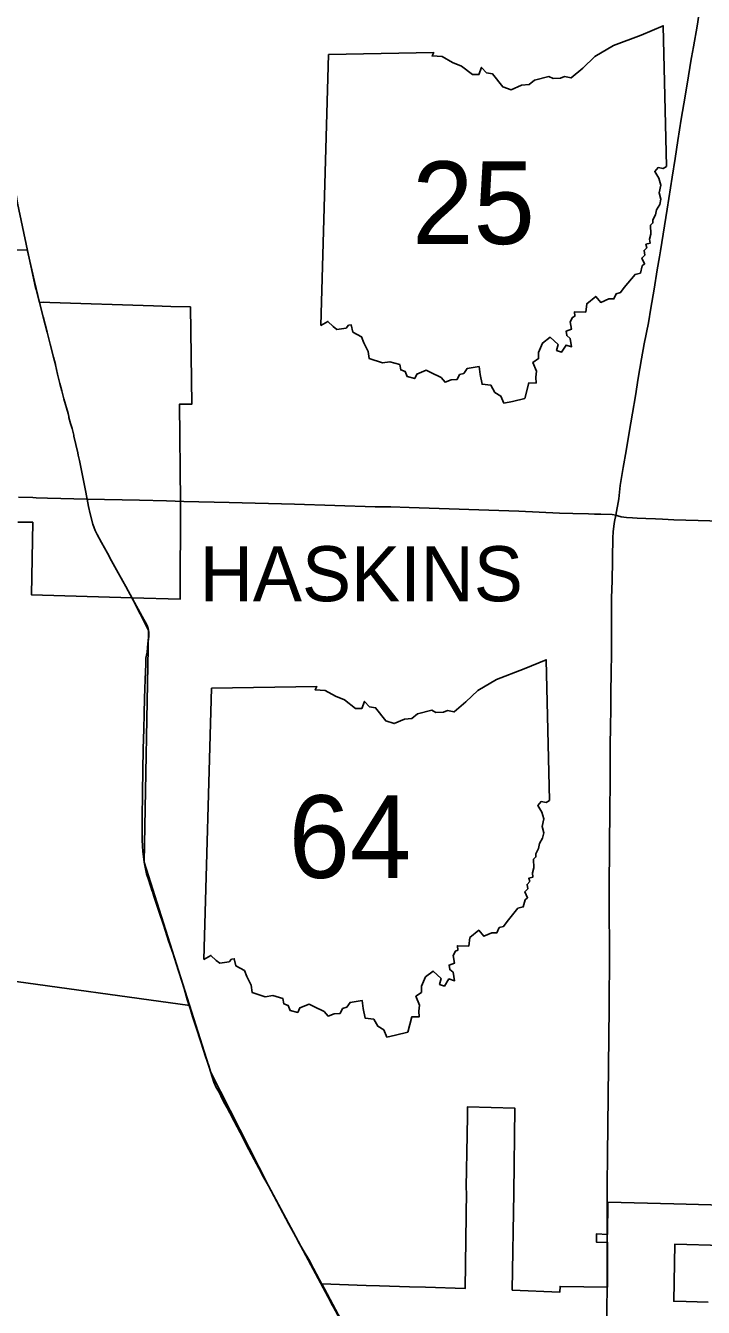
# Model space of a CAD drawing. Extents: x 0 to 851, y 0 to 440.
# Drawn here: x 287.6 to 318.5, y 226.5 to 285 of the extents above; entities that cross this region are included whole.
import ezdxf

# ---------------------------------------------------------------- set-up
doc = ezdxf.new("R2010")
doc.units = 0
for name, color, linetype in [('DV_X_Corp_Line', 7, 'Continuous'), ('GM_X_Corporation_Text', 7, 'Continuous'), ('GM_X_State_Route', 7, 'Continuous'), ('PV_P_Text', 7, 'Continuous'), ('RD_P_Fence', 7, 'Continuous'), ('SH_Data', 7, 'Continuous')]:
    doc.layers.add(name, color=color, linetype=linetype)

msp = doc.modelspace()

# ---------------------------------------------------------------- linework, layer by layer
at = {"layer": 'DV_X_Corp_Line'}
for points in [[(285.628, 274.777), (287.638, 274.782), (287.673, 274.604), (287.962, 273.347), (288.204, 272.386), (288.39, 272.391), (288.666, 272.381), (293.406, 272.229), (294.195, 272.205), (295.084, 272.179), (295.145, 267.74), (294.593, 267.747), (294.636, 263.311), (294.612, 258.847), (292.419, 258.917), (287.825, 259.049), (287.89, 262.358), (287.214, 262.364)], [(303.326, 223.42), (301.088, 227.615), (303.104, 227.549), (303.717, 227.53), (305.091, 227.491), (305.822, 227.467), (307.622, 227.403), (307.687, 231.84), (307.68, 231.909), (307.678, 231.954), (307.677, 232.034), (307.69, 232.835), (307.704, 233.603), (307.734, 235.274), (307.74, 235.698), (309.898, 235.629), (309.843, 231.766), (309.776, 227.337), (311.949, 227.247), (311.958, 227.5), (314.128, 227.473), (314.127, 229.51), (313.616, 229.524), (313.62, 229.896), (314.127, 229.874), (314.134, 231.341), (317.154, 231.265), (319.399, 231.202)], [(319.371, 229.365), (317.197, 229.427), (317.149, 226.828), (317.713, 226.813), (318.72, 226.789)]]:
    msp.add_lwpolyline(points, dxfattribs=at)
at = {"layer": 'GM_X_State_Route'}
for points in [[(317.965, 283.565), (318.056, 284.051), (318.21, 284.99), (318.342, 285.798), (318.465, 286.621), (318.58, 287.355), (318.674, 287.903), (318.734, 288.303), (318.84, 288.954), (318.934, 289.522), (319.023, 290.102), (319.081, 290.432)], [(314.502, 262.675), (314.639, 263.434), (314.703, 264.038), (314.84, 264.849), (314.974, 265.619), (315.115, 266.456), (315.271, 267.334), (315.395, 268.121), (315.529, 268.932), (315.681, 269.816), (315.79, 270.492), (315.997, 271.461), (316.106, 272.124), (316.255, 272.998), (316.397, 273.879), (316.493, 274.459), (316.536, 274.737), (316.724, 275.881), (316.841, 276.641), (316.921, 277.133), (317.075, 278.092), (317.216, 278.949), (317.34, 279.774), (317.491, 280.745), (317.662, 281.791), (317.819, 282.715), (317.949, 283.478), (317.965, 283.565)], [(287.654, 274.76), (287.187, 276.916), (286.85, 279.198), (286.876, 279.819), (286.892, 280.43), (286.918, 281.178), (286.936, 281.82), (286.964, 282.464), (286.986, 282.978), (286.992, 283.339), (286.992, 283.342)], [(287.883, 273.701), (287.654, 274.76)], [(288.036, 272.996), (287.883, 273.701)], [(288.196, 272.384), (288.039, 272.981), (288.036, 272.996)], [(288.927, 269.548), (288.839, 269.883), (288.686, 270.485), (288.551, 271.033), (288.372, 271.728), (288.196, 272.384)], [(289.542, 267.141), (289.531, 267.184), (289.499, 267.325), (289.313, 267.994), (289.221, 268.349), (289.128, 268.686), (289.022, 269.115), (288.929, 269.541), (288.927, 269.548)], [(289.771, 266.284), (289.759, 266.338), (289.688, 266.636), (289.608, 266.867), (289.542, 267.141)], [(289.969, 265.419), (289.944, 265.522), (289.861, 265.903), (289.771, 266.284)], [(290.37, 263.418), (290.287, 263.882), (290.14, 264.564), (290.028, 265.173), (289.969, 265.419)], [(287.241, 263.51), (287.893, 263.485), (288.045, 263.479)], [(288.045, 263.479), (288.56, 263.456), (290.37, 263.418)], [(292.432, 258.882), (292.422, 258.899), (292.244, 259.224), (292.134, 259.428), (292.002, 259.667), (291.714, 260.192), (291.49, 260.603), (291.297, 260.955), (291.034, 261.435), (290.834, 261.807), (290.738, 261.99), (290.696, 262.107), (290.636, 262.27), (290.508, 262.736), (290.441, 263.078), (290.37, 263.418)], [(290.37, 263.418), (290.37, 263.418), (292.768, 263.364), (293.991, 263.331), (294.779, 263.31)], [(294.779, 263.31), (296.848, 263.255), (299.841, 263.178), (303.525, 263.069), (304.241, 263.058), (305.074, 263.039), (310.069, 262.867), (311.933, 262.778), (312.546, 262.758), (313.25, 262.736), (313.53, 262.731)], [(313.53, 262.731), (313.813, 262.726), (314.335, 262.711), (314.502, 262.675)], [(314.205, 245.738), (314.229, 249.324), (314.229, 249.431), (314.241, 250.307), (314.248, 251.318), (314.252, 252.167), (314.267, 253.053), (314.276, 253.814), (314.272, 254.581), (314.284, 255.501), (314.299, 256.351), (314.299, 257.187), (314.307, 258.073), (314.311, 258.896), (314.342, 259.698), (314.352, 260.596), (314.354, 261.034), (314.366, 261.335), (314.368, 261.641), (314.382, 261.919), (314.41, 262.173), (314.441, 262.399), (314.502, 262.675)], [(314.502, 262.675), (314.596, 262.646), (314.747, 262.606), (314.989, 262.58), (315.271, 262.555)], [(315.271, 262.555), (315.472, 262.538), (315.878, 262.523), (316.321, 262.509)], [(316.321, 262.509), (316.63, 262.498), (317.153, 262.476), (317.702, 262.46), (318.268, 262.444), (318.801, 262.422), (319.494, 262.4), (320.053, 262.381), (320.586, 262.365), (321.196, 262.341), (321.765, 262.322), (322.371, 262.302), (323.021, 262.281), (323.647, 262.26), (324.13, 262.246), (324.468, 262.233), (324.803, 262.218), (325.399, 262.187), (325.938, 262.159), (325.958, 262.158), (325.96, 262.158)], [(301.768, 226.305), (301.532, 226.708), (301.343, 227.139), (301.114, 227.552), (300.702, 228.321), (300.487, 228.726), (300.275, 229.075), (300.025, 229.527), (299.875, 229.799), (299.574, 230.348), (299.16, 231.114), (298.906, 231.6), (298.645, 232.097), (298.429, 232.484), (298.211, 232.9), (298.001, 233.293), (297.637, 233.973), (297.363, 234.521), (297.083, 235.047), (296.885, 235.426), (296.766, 235.653), (296.618, 235.901), (296.474, 236.2), (296.363, 236.412), (296.267, 236.582), (296.157, 236.823), (296.021, 237.262), (295.927, 237.558), (295.772, 237.996), (295.563, 238.653), (295.353, 239.309), (295.188, 239.815), (295.087, 240.137), (294.94, 240.587), (294.797, 241.092), (294.696, 241.43), (294.441, 242.225), (294.293, 242.674), (294.09, 243.27), (294.016, 243.502), (293.868, 243.943), (293.629, 244.668), (293.418, 245.303), (293.352, 245.51), (293.343, 245.538), (293.271, 245.768), (293.168, 246.069), (293.087, 246.319), (293.025, 246.624), (292.978, 246.851), (292.942, 247.09), (292.913, 247.336), (292.899, 247.591), (292.882, 247.878), (292.878, 248.305), (292.883, 248.567), (292.889, 249.014), (292.891, 249.236), (292.896, 249.643), (292.902, 250.032), (292.936, 252.029), (292.958, 252.926), (292.977, 253.624), (292.995, 254.329), (293.02, 255.191), (293.045, 255.886), (293.049, 256.161), (293.11, 256.439), (293.146, 256.83), (293.169, 257.029), (293.183, 257.149), (293.189, 257.276), (293.187, 257.344), (293.176, 257.435), (293.162, 257.514), (293.126, 257.607), (293.079, 257.704), (292.962, 257.921), (292.798, 258.229), (292.533, 258.699), (292.432, 258.882)], [(314.109, 232.126), (314.122, 233.491), (314.201, 240.218), (314.216, 242.725), (314.2, 244.884), (314.205, 245.738)], [(314.107, 231.246), (314.107, 231.276), (314.108, 232.041), (314.109, 232.126)], [(314.105, 229.745), (314.107, 231.246)], [(314.102, 227.362), (314.104, 229.392)], [(314.104, 229.392), (314.104, 229.423), (314.105, 229.737), (314.105, 229.745)], [(314.081, 225.01), (314.1, 226.925)], [(314.1, 226.925), (314.101, 227.008), (314.102, 227.362)]]:
    msp.add_lwpolyline(points, dxfattribs=at)
at = {"layer": 'PV_P_Text'}
for p, q in [((301.045, 271.329), (301.391, 283.701)), ((301.045, 271.329), (301.391, 283.701)), ((295.704, 242.416), (296.05, 254.788)), ((295.704, 242.416), (296.05, 254.788))]:
    msp.add_line(p, q, dxfattribs=at)
for points in [[(301.391, 283.701), (306.192, 283.782), (306.117, 283.632), (306.57, 283.601), (307.051, 283.337), (307.458, 283.17), (307.956, 282.776), (308.253, 282.781), (308.379, 283.103), (308.607, 282.854), (308.878, 282.81), (309.346, 282.218), (309.732, 282.089), (310.195, 282.292), (310.541, 282.326), (310.794, 282.526), (311.452, 282.698), (311.636, 282.595), (311.985, 282.616), (312.16, 282.692), (312.465, 282.624), (313, 283.074), (313.551, 283.604), (314.399, 284.105), (315.665, 284.579), (316.667, 285.003), (316.811, 278.582)], [(301.391, 283.701), (306.192, 283.782), (306.117, 283.632), (306.57, 283.601), (307.051, 283.337), (307.458, 283.17), (307.956, 282.776), (308.253, 282.781), (308.379, 283.103), (308.607, 282.854), (308.878, 282.81), (309.346, 282.218), (309.732, 282.089), (310.195, 282.292), (310.541, 282.326), (310.794, 282.526), (311.452, 282.698), (311.636, 282.595), (311.985, 282.616), (312.16, 282.692), (312.465, 282.624), (313, 283.074), (313.551, 283.604), (314.399, 284.105), (315.665, 284.579), (316.667, 285.003), (316.811, 278.582)], [(316.811, 278.582), (316.664, 278.492), (316.433, 278.535), (316.279, 278.355), (316.47, 278.054), (316.561, 277.737), (316.481, 277.387), (316.56, 277.098), (316.506, 276.857), (316.361, 276.616), (316.311, 276.387), (316.189, 276.146), (316.199, 276.011), (316.081, 275.904), (316.103, 275.502), (316.043, 275.279), (316.064, 275.088), (315.874, 275.037), (315.917, 274.879), (315.796, 274.756), (315.822, 274.545), (315.685, 274.411), (315.818, 274.142), (315.711, 274.056), (315.623, 273.728), (315.379, 273.662), (314.891, 273.063), (314.718, 272.836), (314.525, 272.78), (314.418, 272.547), (314.18, 272.546), (313.819, 272.385), (313.586, 272.663), (313.178, 272.329), (313.131, 271.943), (312.614, 271.955), (312.635, 271.76), (312.519, 271.703), (312.414, 271.508), (312.475, 271.161), (312.234, 271.072), (312.263, 270.87), (312.418, 270.747), (312.486, 270.362), (312.23, 270.44), (312.019, 270.115), (311.803, 270.192), (311.873, 270.467), (311.508, 270.797), (311.162, 270.532), (310.981, 270.109), (310.979, 269.824), (310.721, 269.652), (310.887, 269.25), (310.857, 268.973), (310.862, 268.71), (310.539, 268.719), (310.344, 268.008)], [(316.811, 278.582), (316.664, 278.492), (316.433, 278.535), (316.279, 278.355), (316.47, 278.054), (316.561, 277.737), (316.481, 277.387), (316.56, 277.098), (316.506, 276.857), (316.361, 276.616), (316.311, 276.387), (316.189, 276.146), (316.199, 276.011), (316.081, 275.904), (316.103, 275.502), (316.043, 275.279), (316.064, 275.088), (315.874, 275.037), (315.917, 274.879), (315.796, 274.756), (315.822, 274.545), (315.685, 274.411), (315.818, 274.142), (315.711, 274.056), (315.623, 273.728), (315.379, 273.662), (314.891, 273.063), (314.718, 272.836), (314.525, 272.78), (314.418, 272.547), (314.18, 272.546), (313.819, 272.385), (313.586, 272.663), (313.178, 272.329), (313.131, 271.943), (312.614, 271.955), (312.635, 271.76), (312.519, 271.703), (312.414, 271.508), (312.475, 271.161), (312.234, 271.072), (312.263, 270.87), (312.418, 270.747), (312.486, 270.362), (312.23, 270.44), (312.019, 270.115), (311.803, 270.192), (311.873, 270.467), (311.508, 270.797), (311.162, 270.532), (310.981, 270.109), (310.979, 269.824), (310.721, 269.652), (310.887, 269.25), (310.857, 268.973), (310.862, 268.71), (310.539, 268.719), (310.344, 268.008)], [(310.344, 268.008), (309.784, 267.873), (309.395, 267.791), (309.258, 268.114), (308.98, 268.284), (308.799, 268.609), (308.399, 268.653), (308.305, 269.099), (308.26, 269.461), (307.714, 269.372), (307.564, 269.151), (307.371, 269.091), (307.258, 268.868), (306.994, 268.85), (306.711, 268.745), (306.526, 268.963), (306.062, 269.183), (305.853, 269.296), (305.417, 269.12), (305.324, 268.912), (304.976, 269.004), (304.895, 269.236), (304.685, 269.306), (304.639, 269.552), (304.19, 269.683), (303.846, 269.631), (303.24, 269.829), (303.203, 270.154), (302.997, 270.549), (302.889, 270.823), (302.506, 271.033), (302.428, 271.359), (302.306, 271.349), (302.194, 271.217), (301.768, 271.156), (301.598, 271.289), (301.36, 271.517), (301.045, 271.329)], [(310.344, 268.008), (309.784, 267.873), (309.395, 267.791), (309.258, 268.114), (308.98, 268.284), (308.799, 268.609), (308.399, 268.653), (308.305, 269.099), (308.26, 269.461), (307.714, 269.372), (307.564, 269.151), (307.371, 269.091), (307.258, 268.868), (306.994, 268.85), (306.711, 268.745), (306.526, 268.963), (306.062, 269.183), (305.853, 269.296), (305.417, 269.12), (305.324, 268.912), (304.976, 269.004), (304.895, 269.236), (304.685, 269.306), (304.639, 269.552), (304.19, 269.683), (303.846, 269.631), (303.24, 269.829), (303.203, 270.154), (302.997, 270.549), (302.889, 270.823), (302.506, 271.033), (302.428, 271.359), (302.306, 271.349), (302.194, 271.217), (301.768, 271.156), (301.598, 271.289), (301.36, 271.517), (301.045, 271.329)], [(296.05, 254.788), (300.85, 254.869), (300.775, 254.719), (301.229, 254.688), (301.71, 254.423), (302.116, 254.256), (302.614, 253.863), (302.912, 253.867), (303.038, 254.19), (303.266, 253.941), (303.537, 253.897), (304.005, 253.304), (304.391, 253.176), (304.854, 253.379), (305.2, 253.412), (305.452, 253.613), (306.111, 253.785), (306.295, 253.682), (306.643, 253.703), (306.819, 253.779), (307.123, 253.711), (307.659, 254.161), (308.21, 254.691), (309.058, 255.192), (310.324, 255.666), (311.325, 256.09), (311.47, 249.669)], [(296.05, 254.788), (300.85, 254.869), (300.775, 254.719), (301.229, 254.688), (301.71, 254.423), (302.116, 254.256), (302.614, 253.863), (302.912, 253.867), (303.038, 254.19), (303.266, 253.941), (303.537, 253.897), (304.005, 253.304), (304.391, 253.176), (304.854, 253.379), (305.2, 253.412), (305.452, 253.613), (306.111, 253.785), (306.295, 253.682), (306.643, 253.703), (306.819, 253.779), (307.123, 253.711), (307.659, 254.161), (308.21, 254.691), (309.058, 255.192), (310.324, 255.666), (311.325, 256.09), (311.47, 249.669)], [(311.47, 249.669), (311.322, 249.579), (311.092, 249.621), (310.938, 249.441), (311.129, 249.141), (311.219, 248.824), (311.139, 248.474), (311.218, 248.185), (311.164, 247.943), (311.02, 247.703), (310.97, 247.474), (310.847, 247.233), (310.857, 247.097), (310.74, 246.99), (310.761, 246.589), (310.702, 246.366), (310.722, 246.174), (310.532, 246.124), (310.576, 245.965), (310.455, 245.843), (310.481, 245.632), (310.344, 245.498), (310.477, 245.228), (310.37, 245.143), (310.281, 244.815), (310.037, 244.749), (309.549, 244.15), (309.377, 243.923), (309.183, 243.867), (309.077, 243.634), (308.839, 243.633), (308.478, 243.472), (308.245, 243.749), (307.836, 243.415), (307.789, 243.03), (307.273, 243.042), (307.293, 242.847), (307.178, 242.79), (307.073, 242.595), (307.134, 242.247), (306.892, 242.159), (306.921, 241.957), (307.076, 241.834), (307.145, 241.449), (306.888, 241.527), (306.677, 241.202), (306.461, 241.278), (306.532, 241.553), (306.166, 241.884), (305.82, 241.619), (305.64, 241.196), (305.638, 240.911), (305.38, 240.739), (305.545, 240.337), (305.515, 240.06), (305.52, 239.796), (305.198, 239.806), (305.003, 239.095)], [(311.47, 249.669), (311.322, 249.579), (311.092, 249.621), (310.938, 249.441), (311.129, 249.141), (311.219, 248.824), (311.139, 248.474), (311.218, 248.185), (311.164, 247.943), (311.02, 247.703), (310.97, 247.474), (310.847, 247.233), (310.857, 247.097), (310.74, 246.99), (310.761, 246.589), (310.702, 246.366), (310.722, 246.174), (310.532, 246.124), (310.576, 245.965), (310.455, 245.843), (310.481, 245.632), (310.344, 245.498), (310.477, 245.228), (310.37, 245.143), (310.281, 244.815), (310.037, 244.749), (309.549, 244.15), (309.377, 243.923), (309.183, 243.867), (309.077, 243.634), (308.839, 243.633), (308.478, 243.472), (308.245, 243.749), (307.836, 243.415), (307.789, 243.03), (307.273, 243.042), (307.293, 242.847), (307.178, 242.79), (307.073, 242.595), (307.134, 242.247), (306.892, 242.159), (306.921, 241.957), (307.076, 241.834), (307.145, 241.449), (306.888, 241.527), (306.677, 241.202), (306.461, 241.278), (306.532, 241.553), (306.166, 241.884), (305.82, 241.619), (305.64, 241.196), (305.638, 240.911), (305.38, 240.739), (305.545, 240.337), (305.515, 240.06), (305.52, 239.796), (305.198, 239.806), (305.003, 239.095)], [(305.003, 239.095), (304.443, 238.96), (304.054, 238.878), (303.916, 239.201), (303.638, 239.371), (303.457, 239.696), (303.058, 239.74), (302.964, 240.186), (302.919, 240.548), (302.373, 240.459), (302.223, 240.238), (302.029, 240.178), (301.917, 239.955), (301.653, 239.936), (301.37, 239.831), (301.184, 240.05), (300.72, 240.27), (300.512, 240.383), (300.075, 240.207), (299.982, 239.999), (299.635, 240.09), (299.554, 240.323), (299.344, 240.393), (299.297, 240.639), (298.848, 240.77), (298.504, 240.718), (297.898, 240.916), (297.862, 241.241), (297.655, 241.636), (297.547, 241.91), (297.164, 242.119), (297.087, 242.446), (296.964, 242.436), (296.852, 242.304), (296.427, 242.243), (296.257, 242.376), (296.018, 242.604), (295.704, 242.416)], [(305.003, 239.095), (304.443, 238.96), (304.054, 238.878), (303.916, 239.201), (303.638, 239.371), (303.457, 239.696), (303.058, 239.74), (302.964, 240.186), (302.919, 240.548), (302.373, 240.459), (302.223, 240.238), (302.029, 240.178), (301.917, 239.955), (301.653, 239.936), (301.37, 239.831), (301.184, 240.05), (300.72, 240.27), (300.512, 240.383), (300.075, 240.207), (299.982, 239.999), (299.635, 240.09), (299.554, 240.323), (299.344, 240.393), (299.297, 240.639), (298.848, 240.77), (298.504, 240.718), (297.898, 240.916), (297.862, 241.241), (297.655, 241.636), (297.547, 241.91), (297.164, 242.119), (297.087, 242.446), (296.964, 242.436), (296.852, 242.304), (296.427, 242.243), (296.257, 242.376), (296.018, 242.604), (295.704, 242.416)]]:
    msp.add_lwpolyline(points, dxfattribs=at)
at = {"layer": 'RD_P_Fence'}
msp.add_lwpolyline([(303.526, 223.008), (298.645, 232.097), (296.021, 237.262), (292.978, 246.851), (293.176, 257.435), (292.422, 258.899)], dxfattribs=at)
at = {"layer": 'SH_Data'}
msp.add_line((223.462, 250.235), (295.053, 240.313), dxfattribs=at)

# ---------------------------------------------------------------- texts
at = {"layer": 'GM_X_Corporation_Text'}
msp.add_text('HASKINS', height=2.5126, rotation=0.00001, dxfattribs=at).set_placement((295.511, 258.755))
at = {"layer": 'PV_P_Text'}
for s, p in [('25', (305.203, 275.05)), ('64', (299.565, 246.137))]:
    msp.add_text(s, height=3.7688, dxfattribs=at).set_placement(p)

doc.saveas('drawing.dxf')
